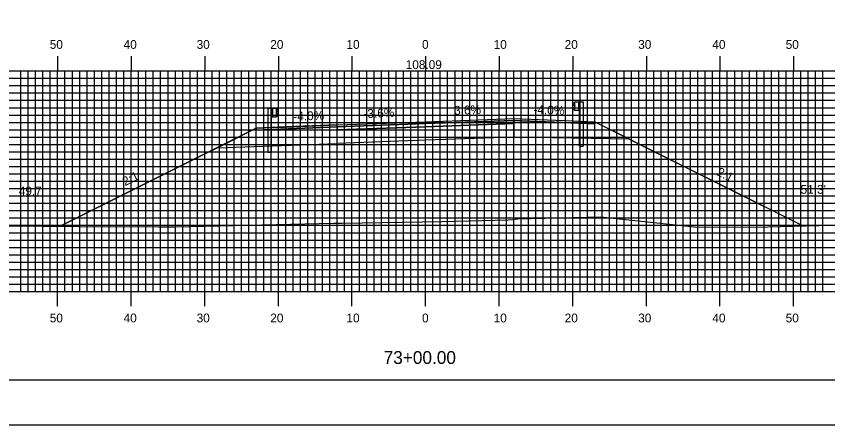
# Model space of a CAD drawing. Extents: x 1761004 to 1761347, y 442591 to 442811.
# Drawn here: x 1761114.1 to 1761224.4, y 442590.5 to 442646.1 of the extents above; entities that cross this region are included whole.
import ezdxf

# ---------------------------------------------------------------- set-up
doc = ezdxf.new("R2010")
doc.units = 0
for name, color, linetype in [('ANNOTATION', 7, 'Continuous'), ('BORDER', 7, 'Continuous'), ('D_Guardrail_Beam_Lt', 7, 'Continuous'), ('D_Guardrail_Beam_Rt', 7, 'Continuous'), ('D_Roadway_Centerline', 7, 'Continuous'), ('D_Roadway_Centerline_Text', 7, 'Continuous'), ('D_Roadway_Edge_Shoulder', 7, 'Continuous'), ('D_Roadway_Edge_TW', 7, 'Continuous'), ('D_Roadway_Pavement', 7, 'Continuous'), ('D_Roadway_SlopeLines', 7, 'Continuous'), ('D_Roadway_SubGrade', 7, 'Continuous'), ('D_Text_Standard', 7, 'Continuous'), ('H_V ANNOTATION', 7, 'Continuous'), ('MAJOR', 7, 'Continuous'), ('MINOR', 7, 'Continuous'), ('PLOT BOUNDARY', 7, 'Continuous'), ('S_Roadway_Centerline', 7, 'Continuous')]:
    doc.layers.add(name, color=color, linetype=linetype)

msp = doc.modelspace()

# ---------------------------------------------------------------- linework, layer by layer
at = {"layer": 'BORDER'}
msp.add_lwpolyline([(1761020.13, 442596.67), (1761340.13, 442596.67), (1761340.13, 442806.67), (1761020.13, 442806.67)], close=True, dxfattribs=at)
at = {"layer": 'D_Guardrail_Beam_Lt'}
for p, q in [((1761148.3, 442633.58), (1761148.3, 442627.58)), ((1761148.77, 442633.58), (1761148.3, 442633.58)), ((1761149.46, 442633.58), (1761148.77, 442633.58)), ((1761148.77, 442633.58), (1761148.77, 442632.41)), ((1761148.83, 442633.58), (1761148.83, 442632.41)), ((1761148.93, 442633.58), (1761148.93, 442632.41)), ((1761149.46, 442632.41), (1761149.46, 442633.58)), ((1761149.46, 442633.5), (1761149.53, 442633.48)), ((1761149.55, 442633.48), (1761149.69, 442633.38)), ((1761148.77, 442632.41), (1761149.46, 442632.41)), ((1761148.79, 442627.58), (1761148.79, 442632.41)), ((1761149.46, 442633.03), (1761149.46, 442632.96)), ((1761149.53, 442632.51), (1761149.46, 442632.5)), ((1761149.69, 442633.23), (1761149.49, 442633.1)), ((1761149.49, 442632.9), (1761149.69, 442632.76)), ((1761149.69, 442632.62), (1761149.55, 442632.52)), ((1761148.79, 442627.58), (1761148.3, 442627.58))]:
    msp.add_line(p, q, dxfattribs=at)
for centre, major_axis, start_param, end_param in [((1761149.52, 442633.44), (0.0417, 0), 0.959931, 1.376053), ((1761149.64, 442633.31), (0.0877, 0), 5.323254, 7.243116), ((1761149.54, 442633.03), (-0.0789, 0), 5.323254, 6.283185), ((1761149.54, 442632.96), (-0.0789, 0), 6.283185, 7.243116), ((1761149.52, 442632.55), (0.0417, 0), 4.907132, 5.323254), ((1761149.64, 442632.69), (0.0877, 0), 5.323254, 7.243116)]:
    msp.add_ellipse(centre, major_axis=major_axis, ratio=0.995501, start_param=start_param, end_param=end_param, dxfattribs=at)
at = {"layer": 'D_Guardrail_Beam_Rt'}
for p, q in [((1761190, 442634.45), (1761190.69, 442634.45)), ((1761190, 442633.28), (1761190, 442634.45)), ((1761190.52, 442634.45), (1761190.52, 442633.28)), ((1761190.62, 442634.45), (1761190.62, 442633.28)), ((1761190.69, 442634.45), (1761191.16, 442634.45)), ((1761190.69, 442634.45), (1761190.69, 442633.28)), ((1761191.16, 442634.45), (1761191.16, 442628.45)), ((1761189.91, 442634.34), (1761189.76, 442634.24)), ((1761189.76, 442634.1), (1761189.96, 442633.96)), ((1761189.96, 442633.76), (1761189.76, 442633.63)), ((1761189.76, 442633.48), (1761189.91, 442633.38)), ((1761190, 442634.36), (1761189.92, 442634.35)), ((1761189.92, 442633.38), (1761190, 442633.36)), ((1761189.99, 442633.9), (1761189.99, 442633.83)), ((1761190.69, 442633.28), (1761190, 442633.28)), ((1761190.66, 442628.45), (1761190.66, 442633.28)), ((1761190.66, 442628.45), (1761191.16, 442628.45))]:
    msp.add_line(p, q, dxfattribs=at)
for centre, major_axis, start_param, end_param in [((1761189.81, 442634.17), (-0.0877, 0), 5.323254, 7.243116), ((1761189.81, 442633.56), (-0.0877, 0), 5.323254, 7.243116), ((1761189.93, 442634.31), (-0.0417, 0), 4.907132, 5.323254), ((1761189.93, 442633.42), (-0.0417, 0), 0.959931, 1.376053), ((1761189.91, 442633.9), (0.0789, 0), 0, 0.959931), ((1761189.91, 442633.83), (0.0789, 0), 5.323254, 6.283185)]:
    msp.add_ellipse(centre, major_axis=major_axis, ratio=0.995501, start_param=start_param, end_param=end_param, dxfattribs=at)
at = {"layer": 'D_Roadway_Centerline'}
msp.add_lwpolyline([(1761120.06, 442617.55), (1761120.08, 442617.56), (1761139.17, 442627.1), (1761141.43, 442628.23), (1761141.43, 442628.23), (1761142.48, 442628.76), (1761146.72, 442630.88), (1761146.73, 442630.88), (1761149.73, 442631), (1761150.58, 442631.03), (1761157.72, 442631.32), (1761157.73, 442631.32), (1761169.73, 442631.75), (1761181.72, 442632.18), (1761181.73, 442632.18), (1761181.73, 442632.18), (1761189.73, 442631.86), (1761192.73, 442631.74), (1761192.73, 442631.74), (1761197.48, 442629.37), (1761197.48, 442629.37), (1761197.49, 442629.36), (1761210.49, 442622.86), (1761221.03, 442617.59), (1761221.04, 442617.58)], dxfattribs=at)
at = {"layer": 'D_Roadway_Edge_Shoulder'}
for points in [[(1761181.73, 442632.18), (1761189.73, 442631.86), (1761189.73, 442631.86), (1761192.73, 442631.74), (1761192.73, 442631.49), (1761181.73, 442631.93)], [(1761157.73, 442631.32), (1761149.73, 442631), (1761149.73, 442631), (1761146.73, 442630.88), (1761146.73, 442630.63), (1761157.73, 442631.07)]]:
    msp.add_lwpolyline(points, close=True, dxfattribs=at)
at = {"layer": 'D_Roadway_Edge_TW'}
msp.add_lwpolyline([(1761157.73, 442631.07), (1761157.73, 442631.32), (1761169.73, 442631.75), (1761181.73, 442632.18), (1761181.73, 442631.93), (1761169.73, 442631.5)], close=True, dxfattribs=at)
at = {"layer": 'D_Roadway_Pavement'}
msp.add_lwpolyline([(1761157.73, 442630.65), (1761157.73, 442631.07), (1761169.73, 442631.5), (1761181.73, 442631.93), (1761181.73, 442631.52), (1761169.73, 442631.08)], close=True, dxfattribs=at)
for points in [[(1761181.73, 442631.93), (1761181.73, 442631.52)], [(1761157.73, 442631.07), (1761157.73, 442630.65)]]:
    msp.add_lwpolyline(points, dxfattribs=at)
at = {"layer": 'D_Roadway_SlopeLines'}
for points in [[(1761192.73, 442631.74), (1761221.04, 442617.58)], [(1761146.73, 442630.88), (1761120.06, 442617.55)]]:
    msp.add_lwpolyline(points, dxfattribs=at)
at = {"layer": 'D_Roadway_SubGrade'}
for points in [[(1761157.73, 442628.82), (1761157.73, 442631.07), (1761157.73, 442630.65), (1761169.73, 442631.08), (1761181.73, 442631.52), (1761181.73, 442631.93), (1761181.73, 442629.68), (1761169.73, 442629.25)], [(1761181.73, 442631.52), (1761181.73, 442631.93), (1761192.73, 442631.49), (1761192.73, 442631.74), (1761197.48, 442629.37), (1761181.73, 442629.68)], [(1761157.73, 442630.65), (1761157.73, 442631.07), (1761146.73, 442630.63), (1761146.73, 442630.88), (1761141.43, 442628.23), (1761157.73, 442628.82)]]:
    msp.add_lwpolyline(points, close=True, dxfattribs=at)
at = {"layer": 'MAJOR'}
for p, q in [((1761119.73, 442640.67), (1761119.73, 442638.67)), ((1761129.73, 442640.67), (1761129.73, 442638.67)), ((1761139.73, 442640.67), (1761139.73, 442638.67)), ((1761149.73, 442640.67), (1761149.73, 442638.67)), ((1761159.73, 442640.67), (1761159.73, 442638.67)), ((1761169.73, 442640.67), (1761169.73, 442638.67)), ((1761179.73, 442640.67), (1761179.73, 442638.67)), ((1761189.73, 442640.67), (1761189.73, 442638.67)), ((1761199.73, 442640.67), (1761199.73, 442638.67)), ((1761209.73, 442640.67), (1761209.73, 442638.67)), ((1761219.73, 442640.67), (1761219.73, 442638.67)), ((1761029.73, 442638.67), (1761309.73, 442638.67)), ((1761029.73, 442638.67), (1761309.73, 442638.67)), ((1761119.73, 442608.67), (1761119.73, 442638.67)), ((1761129.73, 442608.67), (1761129.73, 442638.67)), ((1761139.73, 442608.67), (1761139.73, 442638.67)), ((1761149.73, 442608.67), (1761149.73, 442638.67)), ((1761159.73, 442608.67), (1761159.73, 442638.67)), ((1761169.73, 442608.67), (1761169.73, 442638.67)), ((1761179.73, 442608.67), (1761179.73, 442638.67)), ((1761189.73, 442608.67), (1761189.73, 442638.67)), ((1761199.73, 442608.67), (1761199.73, 442638.67)), ((1761209.73, 442608.67), (1761209.73, 442638.67)), ((1761219.73, 442608.67), (1761219.73, 442638.67)), ((1761029.73, 442633.67), (1761309.73, 442633.67)), ((1761029.73, 442628.67), (1761309.73, 442628.67)), ((1761029.73, 442623.67), (1761309.73, 442623.67)), ((1761029.73, 442618.67), (1761309.73, 442618.67)), ((1761029.73, 442613.67), (1761309.73, 442613.67)), ((1761029.73, 442608.67), (1761309.73, 442608.67)), ((1761029.73, 442608.67), (1761309.73, 442608.67)), ((1761119.73, 442606.66), (1761119.73, 442608.67)), ((1761129.73, 442606.66), (1761129.73, 442608.67)), ((1761139.73, 442606.66), (1761139.73, 442608.67)), ((1761149.73, 442606.66), (1761149.73, 442608.67)), ((1761159.73, 442606.66), (1761159.73, 442608.67)), ((1761169.73, 442606.66), (1761169.73, 442608.67)), ((1761179.73, 442606.66), (1761179.73, 442608.67)), ((1761189.73, 442606.66), (1761189.73, 442608.67)), ((1761199.73, 442606.66), (1761199.73, 442608.67)), ((1761209.73, 442606.66), (1761209.73, 442608.67)), ((1761219.73, 442606.66), (1761219.73, 442608.67))]:
    msp.add_line(p, q, dxfattribs=at)
at = {"layer": 'MINOR'}
for p, q in [((1761114.73, 442608.67), (1761114.73, 442638.67)), ((1761115.73, 442608.67), (1761115.73, 442638.67)), ((1761116.73, 442608.67), (1761116.73, 442638.67)), ((1761117.73, 442608.67), (1761117.73, 442638.67)), ((1761118.73, 442608.67), (1761118.73, 442638.67)), ((1761120.73, 442608.67), (1761120.73, 442638.67)), ((1761121.73, 442608.67), (1761121.73, 442638.67)), ((1761122.73, 442608.67), (1761122.73, 442638.67)), ((1761123.73, 442608.67), (1761123.73, 442638.67)), ((1761124.73, 442608.67), (1761124.73, 442638.67)), ((1761125.73, 442608.67), (1761125.73, 442638.67)), ((1761126.73, 442608.67), (1761126.73, 442638.67)), ((1761127.73, 442608.67), (1761127.73, 442638.67)), ((1761128.73, 442608.67), (1761128.73, 442638.67)), ((1761130.73, 442608.67), (1761130.73, 442638.67)), ((1761131.73, 442608.67), (1761131.73, 442638.67)), ((1761132.73, 442608.67), (1761132.73, 442638.67)), ((1761133.73, 442608.67), (1761133.73, 442638.67)), ((1761134.73, 442608.67), (1761134.73, 442638.67)), ((1761135.73, 442608.67), (1761135.73, 442638.67)), ((1761136.73, 442608.67), (1761136.73, 442638.67)), ((1761137.73, 442608.67), (1761137.73, 442638.67)), ((1761138.73, 442608.67), (1761138.73, 442638.67)), ((1761140.73, 442608.67), (1761140.73, 442638.67)), ((1761141.73, 442608.67), (1761141.73, 442638.67)), ((1761142.73, 442608.67), (1761142.73, 442638.67)), ((1761143.73, 442608.67), (1761143.73, 442638.67)), ((1761144.73, 442608.67), (1761144.73, 442638.67)), ((1761145.73, 442608.67), (1761145.73, 442638.67)), ((1761146.73, 442608.67), (1761146.73, 442638.67)), ((1761147.73, 442608.67), (1761147.73, 442638.67)), ((1761148.73, 442608.67), (1761148.73, 442638.67)), ((1761150.73, 442608.67), (1761150.73, 442638.67)), ((1761151.73, 442608.67), (1761151.73, 442638.67)), ((1761152.73, 442608.67), (1761152.73, 442638.67)), ((1761153.73, 442608.67), (1761153.73, 442638.67)), ((1761154.73, 442608.67), (1761154.73, 442638.67)), ((1761155.73, 442608.67), (1761155.73, 442638.67)), ((1761156.73, 442608.67), (1761156.73, 442638.67)), ((1761157.73, 442608.67), (1761157.73, 442638.67)), ((1761158.73, 442608.67), (1761158.73, 442638.67)), ((1761160.73, 442608.67), (1761160.73, 442638.67)), ((1761161.73, 442608.67), (1761161.73, 442638.67)), ((1761162.73, 442608.67), (1761162.73, 442638.67)), ((1761163.73, 442608.67), (1761163.73, 442638.67)), ((1761164.73, 442608.67), (1761164.73, 442638.67)), ((1761165.73, 442608.67), (1761165.73, 442638.67)), ((1761166.73, 442608.67), (1761166.73, 442638.67)), ((1761167.73, 442608.67), (1761167.73, 442638.67)), ((1761168.73, 442608.67), (1761168.73, 442638.67)), ((1761170.73, 442608.67), (1761170.73, 442638.67)), ((1761171.73, 442608.67), (1761171.73, 442638.67)), ((1761172.73, 442608.67), (1761172.73, 442638.67)), ((1761173.73, 442608.67), (1761173.73, 442638.67)), ((1761174.73, 442608.67), (1761174.73, 442638.67)), ((1761175.73, 442608.67), (1761175.73, 442638.67)), ((1761176.73, 442608.67), (1761176.73, 442638.67)), ((1761177.73, 442608.67), (1761177.73, 442638.67)), ((1761178.73, 442608.67), (1761178.73, 442638.67)), ((1761180.73, 442608.67), (1761180.73, 442638.67)), ((1761181.73, 442608.67), (1761181.73, 442638.67)), ((1761182.73, 442608.67), (1761182.73, 442638.67)), ((1761183.73, 442608.67), (1761183.73, 442638.67)), ((1761184.73, 442608.67), (1761184.73, 442638.67)), ((1761185.73, 442608.67), (1761185.73, 442638.67)), ((1761186.73, 442608.67), (1761186.73, 442638.67)), ((1761187.73, 442608.67), (1761187.73, 442638.67)), ((1761188.73, 442608.67), (1761188.73, 442638.67)), ((1761190.73, 442608.67), (1761190.73, 442638.67)), ((1761191.73, 442608.67), (1761191.73, 442638.67)), ((1761192.73, 442608.67), (1761192.73, 442638.67)), ((1761193.73, 442608.67), (1761193.73, 442638.67)), ((1761194.73, 442608.67), (1761194.73, 442638.67)), ((1761195.73, 442608.67), (1761195.73, 442638.67)), ((1761196.73, 442608.67), (1761196.73, 442638.67)), ((1761197.73, 442608.67), (1761197.73, 442638.67)), ((1761198.73, 442608.67), (1761198.73, 442638.67)), ((1761200.73, 442608.67), (1761200.73, 442638.67)), ((1761201.73, 442608.67), (1761201.73, 442638.67)), ((1761202.73, 442608.67), (1761202.73, 442638.67)), ((1761203.73, 442608.67), (1761203.73, 442638.67)), ((1761204.73, 442608.67), (1761204.73, 442638.67)), ((1761205.73, 442608.67), (1761205.73, 442638.67)), ((1761206.73, 442608.67), (1761206.73, 442638.67)), ((1761207.73, 442608.67), (1761207.73, 442638.67)), ((1761208.73, 442608.67), (1761208.73, 442638.67)), ((1761210.73, 442608.67), (1761210.73, 442638.67)), ((1761211.73, 442608.67), (1761211.73, 442638.67)), ((1761212.73, 442608.67), (1761212.73, 442638.67)), ((1761213.73, 442608.67), (1761213.73, 442638.67)), ((1761214.73, 442608.67), (1761214.73, 442638.67)), ((1761215.73, 442608.67), (1761215.73, 442638.67)), ((1761216.73, 442608.67), (1761216.73, 442638.67)), ((1761217.73, 442608.67), (1761217.73, 442638.67)), ((1761218.73, 442608.67), (1761218.73, 442638.67)), ((1761220.73, 442608.67), (1761220.73, 442638.67)), ((1761221.73, 442608.67), (1761221.73, 442638.67)), ((1761222.73, 442608.67), (1761222.73, 442638.67)), ((1761223.73, 442608.67), (1761223.73, 442638.67)), ((1761029.73, 442637.67), (1761309.73, 442637.67)), ((1761029.73, 442636.67), (1761309.73, 442636.67)), ((1761029.73, 442635.67), (1761309.73, 442635.67)), ((1761029.73, 442634.67), (1761309.73, 442634.67)), ((1761029.73, 442632.67), (1761309.73, 442632.67)), ((1761029.73, 442631.67), (1761309.73, 442631.67)), ((1761029.73, 442630.67), (1761309.73, 442630.67)), ((1761029.73, 442629.67), (1761309.73, 442629.67)), ((1761029.73, 442627.67), (1761309.73, 442627.67)), ((1761029.73, 442626.67), (1761309.73, 442626.67)), ((1761029.73, 442625.67), (1761309.73, 442625.67)), ((1761029.73, 442624.67), (1761309.73, 442624.67)), ((1761029.73, 442622.67), (1761309.73, 442622.67)), ((1761029.73, 442621.67), (1761309.73, 442621.67)), ((1761029.73, 442620.67), (1761309.73, 442620.67)), ((1761029.73, 442619.67), (1761309.73, 442619.67)), ((1761029.73, 442617.67), (1761309.73, 442617.67)), ((1761029.73, 442616.67), (1761309.73, 442616.67)), ((1761029.73, 442615.67), (1761309.73, 442615.67)), ((1761029.73, 442614.67), (1761309.73, 442614.67)), ((1761029.73, 442612.67), (1761309.73, 442612.67)), ((1761029.73, 442611.67), (1761309.73, 442611.67)), ((1761029.73, 442610.67), (1761309.73, 442610.67)), ((1761029.73, 442609.67), (1761309.73, 442609.67))]:
    msp.add_line(p, q, dxfattribs=at)
at = {"layer": 'PLOT BOUNDARY'}
msp.add_lwpolyline([(1761003.94, 442590.55), (1761343.94, 442590.55), (1761343.94, 442810.55), (1761003.94, 442810.55)], close=True, dxfattribs=at)
at = {"layer": 'S_Roadway_Centerline'}
msp.add_lwpolyline([(1761112.77, 442617.6), (1761122.62, 442617.53), (1761133.5, 442617.46), (1761134.69, 442617.47), (1761135.77, 442617.48), (1761157.23, 442617.96), (1761158.39, 442617.98), (1761171.97, 442618.19), (1761180.93, 442618.44), (1761181.58, 442618.46), (1761182.24, 442618.54), (1761193.52, 442618.82), (1761204.15, 442617.68), (1761206.63, 442617.42), (1761216.23, 442617.46), (1761226.62, 442617.73)], dxfattribs=at)

# ---------------------------------------------------------------- texts
at = {"layer": 'ANNOTATION'}
for s, rotation, p in [('-3.6%', 2.0617, (1761161.31, 442632.25)), ('3.6%', 2.0617, (1761173.63, 442632.69)), ('-4.0%', 357.7093, (1761184.37, 442632.85)), ('-4.0%', 2.2905, (1761151.78, 442631.88)), ('2:1', 26.5644, (1761128.9, 442623)), ('2:1', 333.4333, (1761209.19, 442624.54))]:
    msp.add_text(s, height=1.2, rotation=rotation, dxfattribs=at).set_placement(p)
at = {"layer": 'D_Roadway_Centerline'}
for s, p in [('C', (1761169.72, 442631.75)), ('L', (1761169.73, 442631.74))]:
    msp.add_text(s, height=0.0146, dxfattribs=at).set_placement(p)
at = {"layer": 'D_Roadway_Centerline_Text'}
msp.add_text('108.09', height=1.2, dxfattribs=at).set_placement((1761167.03, 442638.92))
at = {"layer": 'D_Text_Standard'}
for s, p in [("49.7'", (1761114.45, 442621.74)), ("51.3'", (1761220.69, 442621.96))]:
    msp.add_text(s, height=1.2, dxfattribs=at).set_placement(p)
at = {"layer": 'H_V ANNOTATION'}
for s, height, p in [('50', 1.2, (1761118.66, 442641.67)), ('40', 1.2, (1761128.7, 442641.67)), ('30', 1.2, (1761138.62, 442641.67)), ('20', 1.2, (1761148.63, 442641.67)), ('10', 1.2, (1761158.98, 442641.67)), ('0', 1.2, (1761169.25, 442641.67)), ('10', 1.2, (1761178.98, 442641.67)), ('20', 1.2, (1761188.63, 442641.67)), ('30', 1.2, (1761198.62, 442641.67)), ('40', 1.2, (1761208.7, 442641.67)), ('50', 1.2, (1761218.66, 442641.67)), ('50', 1.2, (1761118.66, 442604.47)), ('40', 1.2, (1761128.7, 442604.47)), ('30', 1.2, (1761138.62, 442604.47)), ('20', 1.2, (1761148.63, 442604.47)), ('10', 1.2, (1761158.98, 442604.47)), ('0', 1.2, (1761169.25, 442604.47)), ('10', 1.2, (1761178.98, 442604.47)), ('20', 1.2, (1761188.63, 442604.47)), ('30', 1.2, (1761198.62, 442604.47)), ('40', 1.2, (1761208.7, 442604.47)), ('50', 1.2, (1761218.66, 442604.47)), ('73+00.00', 1.75, (1761164.03, 442598.82))]:
    msp.add_text(s, height=height, dxfattribs=at).set_placement(p)

doc.saveas('drawing.dxf')
